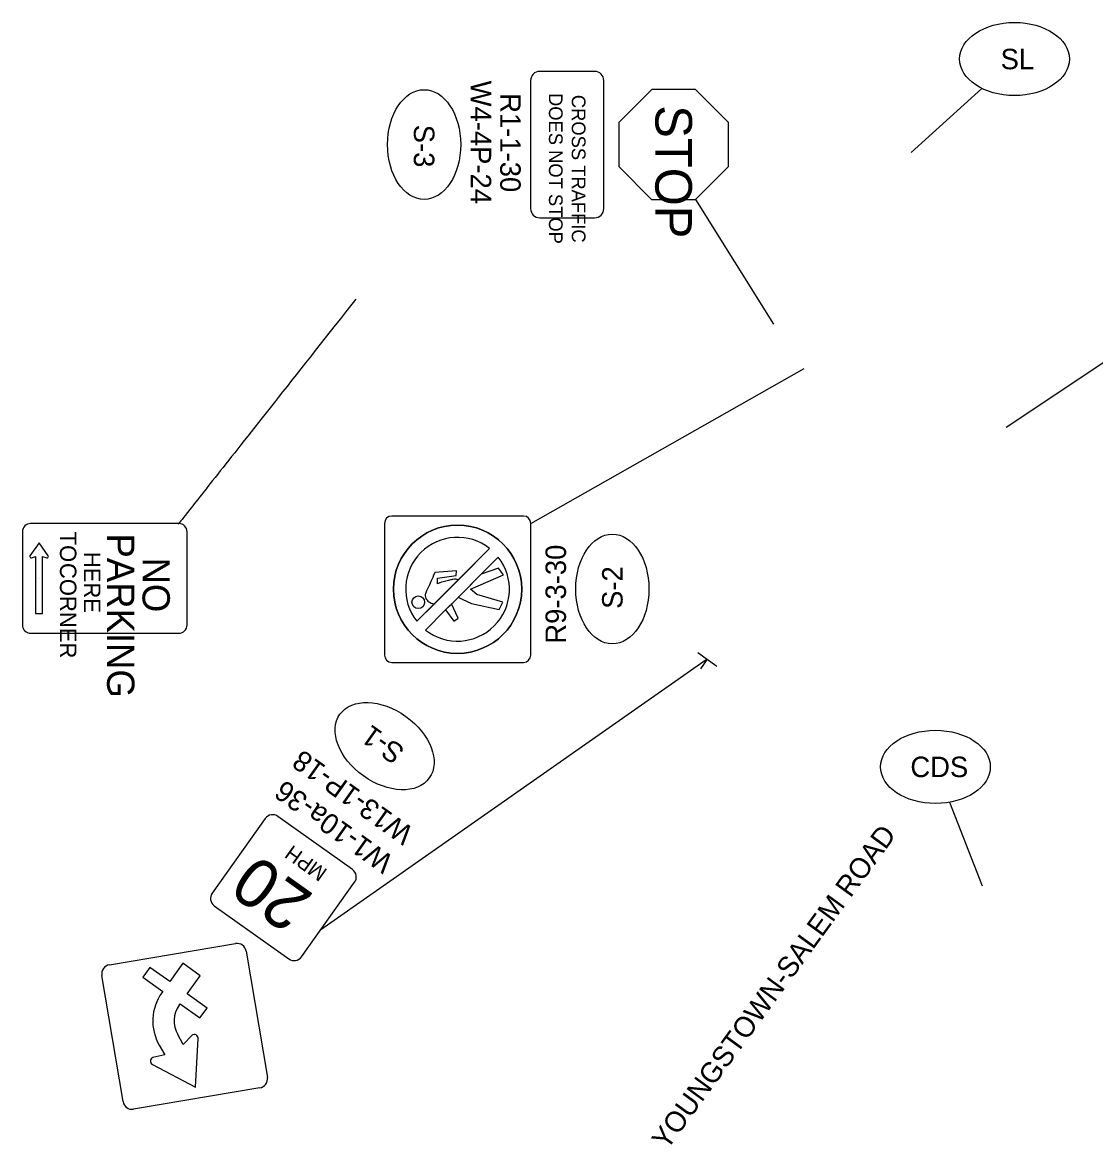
# Model space of a CAD drawing. Extents: x 108269 to 109415, y 548506 to 548874.
# Drawn here: x 108268.7 to 108341.9, y 548683.2 to 548759.8 of the extents above; entities that cross this region are included whole.
import ezdxf

# ---------------------------------------------------------------- set-up
doc = ezdxf.new("R2010")
doc.units = 0
for name, color, linetype in [('Default', 7, 'Continuous'), ('PM_P_Removal', 7, 'Continuous'), ('SH_Data', 7, 'Continuous'), ('SH_Text', 7, 'Continuous'), ('SN_P_Post', 7, 'Continuous'), ('SN_P_Signs', 7, 'Continuous'), ('SN_P_Text', 7, 'Continuous'), ('SN_X_Public', 7, 'Continuous')]:
    doc.layers.add(name, color=color, linetype=linetype)

msp = doc.modelspace()

# ---------------------------------------------------------------- linework, layer by layer
at = {"layer": 'Default'}
for p, q in [((108329.416, 548750.942), (108334.254, 548755.321)), ((108335.904, 548732.189), (108346.233, 548739.068)), ((108332.026, 548706.547), (108334.274, 548700.847))]:
    msp.add_line(p, q, dxfattribs=at)
for centre, major_axis in [((108296.124, 548751.49), (0, -3.75)), ((108308.989, 548721.12), (0, 3.75)), ((108293.424, 548710.382), (-3.054, 2.176))]:
    msp.add_ellipse(centre, major_axis=major_axis, ratio=0.666667, dxfattribs=at)
at = {"layer": 'PM_P_Removal'}
for centre in [(108336.477, 548757.334), (108331.073, 548708.965)]:
    msp.add_ellipse(centre, major_axis=(3.75, 0), ratio=0.666667, dxfattribs=at)
at = {"layer": 'SH_Data'}
msp.add_open_spline([(108291.448, 548740.917), (108279.357, 548725.593), (108279.357, 548725.593), (108279.357, 548725.593)], degree=2, dxfattribs=at)
at = {"layer": 'SH_Text'}
for p, q in [((108314.676, 548747.742), (108319.995, 548739.211)), ((108303.416, 548725.605), (108322.11, 548736.177)), ((108315.475, 548716.32), (108289.057, 548697.83))]:
    msp.add_line(p, q, dxfattribs=at)
at = {"layer": 'SN_P_Post'}
for p, q in [((108314.823, 548716.784), (108316.126, 548715.856)), ((108315.475, 548716.32), (108315.011, 548715.668)), ((108315.474, 548716.32), (108315.474, 548716.32))]:
    msp.add_line(p, q, dxfattribs=at)
at = {"layer": 'SN_P_Signs'}
for p, q in [((108311.681, 548755.244), (108309.43, 548752.996)), ((108314.681, 548755.242), (108311.681, 548755.244)), ((108316.93, 548752.99), (108314.681, 548755.242)), ((108309.43, 548752.996), (108309.427, 548749.996)), ((108316.927, 548749.99), (108316.93, 548752.99)), ((108309.427, 548749.996), (108311.676, 548747.744)), ((108314.676, 548747.742), (108316.927, 548749.99)), ((108311.676, 548747.744), (108314.676, 548747.742)), ((108295.622, 548718.913), (108300.604, 548723.89)), ((108298.343, 548722.352), (108296.847, 548722.238)), ((108298.343, 548722.352), (108296.847, 548722.238)), ((108296.847, 548722.238), (108296.847, 548722.229)), ((108296.847, 548722.238), (108296.847, 548722.229)), ((108298.316, 548722.033), (108298.343, 548722.352)), ((108298.316, 548722.033), (108298.343, 548722.352)), ((108300.031, 548722.135), (108298.489, 548720.591)), ((108301.206, 548722.534), (108300.031, 548722.135)), ((108301.206, 548722.534), (108300.031, 548722.135)), ((108301.542, 548722.09), (108301.206, 548722.534)), ((108301.542, 548722.09), (108301.206, 548722.534)), ((108296.847, 548720.138), (108298.457, 548721.748)), ((108297.033, 548721.484), (108297.048, 548721.849)), ((108297.033, 548721.484), (108297.048, 548721.849)), ((108297.048, 548721.849), (108298.316, 548722.033)), ((108297.048, 548721.849), (108298.316, 548722.033)), ((108299.285, 548721.105), (108301.542, 548722.09)), ((108299.285, 548721.105), (108301.542, 548722.09)), ((108298.489, 548720.591), (108298.46, 548720.561)), ((108299.737, 548720.748), (108299.285, 548721.105)), ((108299.737, 548720.748), (108299.285, 548721.105)), ((108301.501, 548720.225), (108299.737, 548720.748)), ((108301.501, 548720.225), (108299.737, 548720.748)), ((108296.794, 548720.085), (108296.846, 548720.138)), ((108298.001, 548720.101), (108297.918, 548720.018)), ((108298.457, 548719.12), (108298.001, 548720.101)), ((108298.457, 548719.12), (108298.001, 548720.101)), ((108298.46, 548720.561), (108298.715, 548720.427)), ((108298.46, 548720.561), (108298.715, 548720.427)), ((108298.715, 548720.427), (108299.359, 548720.127)), ((108298.715, 548720.427), (108299.359, 548720.127)), ((108299.359, 548720.127), (108301.246, 548719.711)), ((108299.359, 548720.127), (108301.246, 548719.711)), ((108301.246, 548719.711), (108301.501, 548720.225)), ((108301.246, 548719.711), (108301.501, 548720.225)), ((108297.588, 548719.688), (108298.166, 548718.917)), ((108297.588, 548719.687), (108298.166, 548718.917)), ((108298.166, 548718.917), (108298.457, 548719.12)), ((108298.166, 548718.917), (108298.457, 548719.12)), ((108285.264, 548705.433), (108281.638, 548700.342)), ((108291.226, 548701.953), (108286.136, 548705.579)), ((108287.747, 548695.991), (108291.373, 548701.081)), ((108281.785, 548699.471), (108286.875, 548695.844)), ((108277.383, 548695.266), (108276.899, 548694.588)), ((108278.74, 548694.299), (108277.383, 548695.266)), ((108279.627, 548695.544), (108278.74, 548694.299)), ((108280.815, 548694.698), (108279.627, 548695.544)), ((108276.899, 548694.588), (108278.257, 548693.621)), ((108279.928, 548693.453), (108280.815, 548694.698)), ((108278.257, 548693.621), (108278.196, 548693.536)), ((108281.286, 548692.486), (108279.928, 548693.453)), ((108279.384, 548692.69), (108279.445, 548692.774)), ((108279.445, 548692.774), (108280.802, 548691.807)), ((108280.802, 548691.807), (108281.286, 548692.486)), ((108279.666, 548690.004), (108279.284, 548690.67)), ((108278.019, 548689.946), (108278.393, 548689.292)), ((108280.261, 548690.624), (108279.666, 548690.004)), ((108280.502, 548687.076), (108280.674, 548690.407)), ((108278.393, 548689.292), (108277.574, 548689.102)), ((108277.55, 548688.635), (108277.549, 548688.633)), ((108277.549, 548688.633), (108280.502, 548687.076))]:
    msp.add_line(p, q, dxfattribs=at)
for points in [[(108303.404, 548755.865), (108303.404, 548747.115)], [(108307.779, 548756.49), (108304.029, 548756.49)], [(108308.404, 548747.115), (108308.404, 548755.865)], [(108304.029, 548746.49), (108307.779, 548746.49)], [(108302.916, 548726.105), (108293.916, 548726.105)], [(108293.416, 548725.605), (108293.416, 548716.605)], [(108303.416, 548716.605), (108303.416, 548725.605)], [(108300.601, 548723.892), (108298.626, 548721.917), (108298.626, 548721.916), (108298.625, 548721.916), (108296.847, 548720.138), (108296.847, 548720.137)], [(108297.918, 548720.018), (108298.489, 548720.591), (108300.341, 548722.445), (108301.194, 548723.3)], [(108296.846, 548720.138), (108295.622, 548718.913)], [(108296.219, 548718.316), (108297.572, 548719.671), (108297.915, 548720.021), (108297.918, 548720.018)], [(108296.846, 548720.138), (108296.847, 548720.138)], [(108297.918, 548720.018), (108297.588, 548719.687), (108297.588, 548719.687)], [(108293.916, 548716.105), (108302.916, 548716.105)], [(108274.611, 548695.439), (108283.24, 548696.889)], [(108283.96, 548696.376), (108285.409, 548687.747)], [(108275.547, 548686.09), (108274.098, 548694.719)], [(108284.896, 548687.027), (108276.267, 548685.577)]]:
    msp.add_lwpolyline(points, dxfattribs=at)
for centre, radius in [((108298.409, 548721.105), 4.383), ((108295.723, 548720.218), 0.432)]:
    msp.add_circle(centre, radius, dxfattribs=at)
for centre, radius, start, end in [((108304.029, 548755.865), 0.625, 90, 180), ((108307.779, 548755.865), 0.625, 360, 90), ((108304.029, 548747.115), 0.625, 180, 270), ((108307.779, 548747.115), 0.625, 270, 360), ((108293.916, 548725.605), 0.5, 90, 180), ((108302.916, 548725.605), 0.5, 360, 90), ((108298.409, 548721.105), 4.383, 90, 270), ((108298.409, 548721.105), 4.383, 270, 90), ((108298.409, 548721.105), 3.546, 51.81908, 218.17134), ((108298.409, 548721.105), 3.546, 51.81908, 218.17134), ((108298.409, 548721.105), 3.546, 231.84792, 38.24795), ((108298.409, 548721.105), 3.546, 231.84792, 38.24795), ((108297.318, 548720.743), 0.768, 232.07518, 232.12834), ((108293.916, 548716.605), 0.5, 180, 270), ((108302.916, 548716.605), 0.5, 270, 360), ((108285.774, 548705.07), 0.625, 54.53646, 144.53646), ((108290.864, 548701.443), 0.625, 324.53646, 54.53646), ((108282.147, 548699.979), 0.625, 144.53646, 234.53646), ((108283.343, 548696.272), 0.625, 9.53646, 99.53646), ((108274.714, 548694.823), 0.625, 99.53646, 189.53646), ((108287.238, 548696.353), 0.625, 234.53646, 324.53646), ((108280.911, 548691.602), 3.333, 144.53646, 209.79253), ((108280.911, 548691.602), 1.875, 144.53646, 209.79253), ((108280.422, 548690.423), 0.256, 356.52542, 128.7516), ((108277.668, 548688.862), 0.256, 110.32132, 242.5475), ((108284.793, 548687.643), 0.625, 279.53646, 9.53646), ((108276.164, 548686.194), 0.625, 189.53646, 279.53646)]:
    msp.add_arc(centre, radius, start, end, dxfattribs=at)
for points in [[(108296.847, 548722.229), (108296.653, 548721.788), (108296.336, 548721.093), (108296.22, 548720.839), (108296.203, 548720.755), (108296.203, 548720.67), (108296.203, 548720.47), (108296.44, 548720.218), (108296.659, 548720.138), (108296.794, 548720.085)], [(108296.847, 548722.229), (108296.653, 548721.788), (108296.336, 548721.093), (108296.22, 548720.839), (108296.203, 548720.755), (108296.203, 548720.67), (108296.203, 548720.47), (108296.44, 548720.218), (108296.659, 548720.138), (108296.794, 548720.085)], [(108298.457, 548721.748), (108298.422, 548721.764), (108298.319, 548721.797), (108298.09, 548721.779), (108297.883, 548721.737), (108297.521, 548721.638), (108297.27, 548721.562), (108297.033, 548721.484)], [(108298.457, 548721.748), (108298.422, 548721.764), (108298.319, 548721.797), (108298.09, 548721.779), (108297.883, 548721.737), (108297.521, 548721.638), (108297.27, 548721.562), (108297.033, 548721.484)]]:
    msp.add_open_spline(points, degree=3, dxfattribs=at)
at = {"layer": 'SN_X_Public'}
for p, q in [((108269.808, 548724.279), (108269.186, 548723.394)), ((108270.429, 548723.394), (108269.808, 548724.279)), ((108269.288, 548723.254), (108269.573, 548723.345)), ((108269.573, 548723.345), (108269.573, 548723.341)), ((108269.573, 548723.341), (108269.573, 548719.435)), ((108270.042, 548723.345), (108270.327, 548723.254)), ((108269.808, 548721.857), (108269.808, 548721.857)), ((108269.573, 548719.435), (108270.042, 548719.435))]:
    msp.add_line(p, q, dxfattribs=at)
for points in [[(108279.357, 548725.593), (108269.232, 548725.593)], [(108268.67, 548725.03), (108268.67, 548718.655)], [(108279.92, 548718.655), (108279.92, 548725.03)], [(108270.042, 548719.435), (108270.042, 548723.341)], [(108269.232, 548718.093), (108279.357, 548718.093)]]:
    msp.add_lwpolyline(points, dxfattribs=at)
for centre, radius, start, end in [((108269.232, 548725.03), 0.562, 90, 180), ((108279.357, 548725.03), 0.562, 360, 90), ((108269.261, 548723.341), 0.0912, 144.92075, 287.6378), ((108270.354, 548723.341), 0.0912, 252.3622, 35.07924), ((108269.232, 548718.655), 0.562, 180, 270), ((108279.357, 548718.655), 0.562, 270, 360)]:
    msp.add_arc(centre, radius, start, end, dxfattribs=at)

# ---------------------------------------------------------------- texts
at = {"layer": 'Default'}
for s, rotation, p in [('S-3', 270, (108295.424, 548752.845)), ('S-2', 90, (108309.689, 548719.761)), ('S-1', 144.53646, (108294.885, 548710.201))]:
    msp.add_text(s, height=1.4, rotation=rotation, dxfattribs=at).set_placement(p)
at = {"layer": 'PM_P_Removal'}
for s, p in [('SL', (108335.526, 548756.634)), ('CDS', (108329.36, 548708.265))]:
    msp.add_text(s, height=1.4, dxfattribs=at).set_placement(p)
at = {"layer": 'SN_P_Signs'}
for s, height, rotation, p in [('DOES NOT STOP', 0.9375, 270, (108304.654, 548755.013)), ('CROSS TRAFFIC', 0.9375, 270, (108306.216, 548754.887)), ('STOP', 2.5, 269.95531, (108311.931, 548754.178)), ('MPH', 1.0213, 144.53646, (108289.576, 548701.908)), ('20', 3.3333, 144.53646, (108288.663, 548700.198))]:
    msp.add_text(s, height=height, rotation=rotation, dxfattribs=at).set_placement(p)
at = {"layer": 'SN_P_Text'}
for s, rotation, p in [('W4-4P-24', 270, (108299.309, 548755.856)), ('R1-1-30', 270, (108301.323, 548754.997)), ('R9-3-30', 90, (108305.822, 548717.385)), ('W13-1P-18', 144.53646, (108295.5, 548704.7)), ('W1-10a-36', 144.53646, (108294.124, 548702.751)), ('YOUNGSTOWN-SALEM ROAD', 53.95125, (108312.717, 548682.723))]:
    msp.add_text(s, height=1.4, rotation=rotation, dxfattribs=at).set_placement(p)
at = {"layer": 'SN_X_Public'}
for s, height, p in [('TO', 1.125, (108271.232, 548725.042)), ('PARKING', 1.8656, (108274.456, 548724.913)), ('HERE', 1.125, (108272.873, 548723.661)), ('NO', 1.8656, (108276.877, 548723.271)), ('CORNER', 1.125, (108271.232, 548722.9))]:
    msp.add_text(s, height=height, rotation=270, dxfattribs=at).set_placement(p)

doc.saveas('drawing.dxf')
